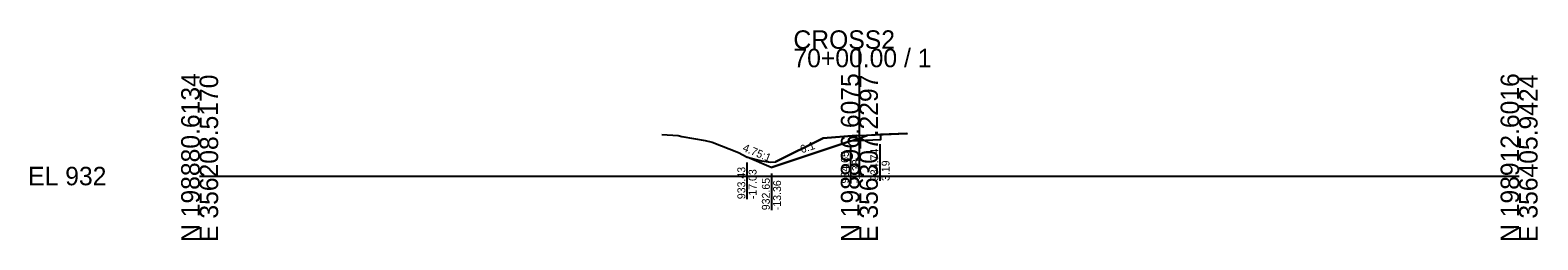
# Model space of a CAD drawing. Extents: x -26 to 203, y -10 to 14021.
# Drawn here: x -25.7 to 202.8, y 10990.3 to 11022.2 of the extents above; entities that cross this region are included whole.
import ezdxf

# ---------------------------------------------------------------- set-up
doc = ezdxf.new("R2010")
doc.units = 0
for name, color, linetype in [('Default', 7, 'Continuous'), ('P_E_XS_Ground', 7, 'Continuous'), ('P_XS', 7, 'Continuous'), ('P_XS_EAR_CommonGrnd', 7, 'Continuous'), ('P_XS_Lane', 7, 'Continuous'), ('P_XS_Rock', 7, 'Continuous')]:
    doc.layers.add(name, color=color, linetype=linetype)

msp = doc.modelspace()

# ---------------------------------------------------------------- linework, layer by layer
at = {"layer": 'Default'}
for p, q in [((100, 11000), (100, 11019.32)), ((0, 11000), (100, 11000)), ((100, 11000), (200, 11000))]:
    msp.add_line(p, q, dxfattribs=at)
at = {"layer": 'P_E_XS_Ground'}
for p, q in [((70.04, 11006.31), (72.51, 11006.15)), ((72.51, 11006.15), (73.08, 11005.98)), ((99.5, 11006.16), (94.5, 11005.76)), ((99.5, 11006.16), (100, 11006.18)), ((100, 11006.18), (107.19, 11006.47)), ((107.19, 11006.47), (107.27, 11006.49)), ((73.08, 11005.98), (76.62, 11005.42)), ((76.62, 11005.42), (77.66, 11005.14)), ((77.66, 11005.14), (81.68, 11003.56)), ((94.5, 11005.76), (87.3, 11002.16)), ((81.68, 11003.56), (82.97, 11002.85)), ((82.97, 11002.85), (85.17, 11002.3)), ((85.17, 11002.3), (86.52, 11002.09)), ((86.52, 11002.09), (87.3, 11002.16))]:
    msp.add_line(p, q, dxfattribs=at)
at = {"layer": 'P_XS'}
for p, q in [((98.62, 11005.29), (101.19, 11006.15)), ((103.19, 11006.31), (101.19, 11006.15)), ((107.19, 11006.47), (103.19, 11006.31))]:
    msp.add_line(p, q, dxfattribs=at)
at = {"layer": 'P_XS_EAR_CommonGrnd'}
msp.add_lwpolyline([(99.5, 11006.16), (100, 11006.18), (103.19, 11006.31), (103.19, 11005.48), (98.62, 11005.29), (86.64, 11001.3), (82.97, 11002.85), (85.17, 11002.3), (86.52, 11002.09), (87.3, 11002.16), (94.5, 11005.76)], close=True, dxfattribs=at)
at = {"layer": 'P_XS_Lane'}
for p, q in [((103.19, 11006.31), (103.19, 11005.48)), ((86.64, 11001.3), (98.62, 11005.29)), ((103.19, 11005.48), (98.62, 11005.29)), ((86.64, 11001.3), (82.97, 11002.85))]:
    msp.add_line(p, q, dxfattribs=at)
at = {"layer": 'P_XS_Rock'}
for p, q in [((98.65, 11004.48), (98.65, 10998.88)), ((103.12, 11004.84), (103.12, 10999.25)), ((82.96, 11002.08), (82.96, 10996.49)), ((86.67, 11000.41), (86.67, 10994.81))]:
    msp.add_line(p, q, dxfattribs=at)

# ---------------------------------------------------------------- texts
at = {"layer": 'Default'}
for s, p in [('CROSS2', (90, 11019.32)), ('70+00.00 / 1', (90, 11016.52)), ('EL 932', (-26, 10998.6))]:
    msp.add_text(s, height=2.8, dxfattribs=at).set_placement(p)
for s, p in [('N 198880.6134', (0, 10990)), ('N 198896.6075', (100, 10990)), ('N 198912.6016', (200, 10990)), ('E 356405.9424', (202.8, 10990)), ('E 356208.5170', (2.8, 10990)), ('E 356307.2297', (102.8, 10990))]:
    msp.add_text(s, height=2.8, rotation=90, dxfattribs=at).set_placement(p)
at = {"layer": 'P_XS_Rock'}
for s, rotation, p in [('4.75:1', 337.0865, (82.2, 11003.86)), ('6:1', 18.4349, (91.26, 11003.44)), ('934.74', 90, (102.87, 10999.25)), ('934.65', 90, (98.4, 10998.88)), ('-1.38', 90, (100.1, 10998.88)), ('3.19', 90, (104.57, 10999.25)), ('933.43', 90, (82.71, 10996.49)), ('-17.03', 90, (84.41, 10996.49)), ('932.65', 90, (86.42, 10994.81)), ('-13.36', 90, (88.12, 10994.81))]:
    msp.add_text(s, height=1.2, rotation=rotation, dxfattribs=at).set_placement(p)

doc.saveas('drawing.dxf')
